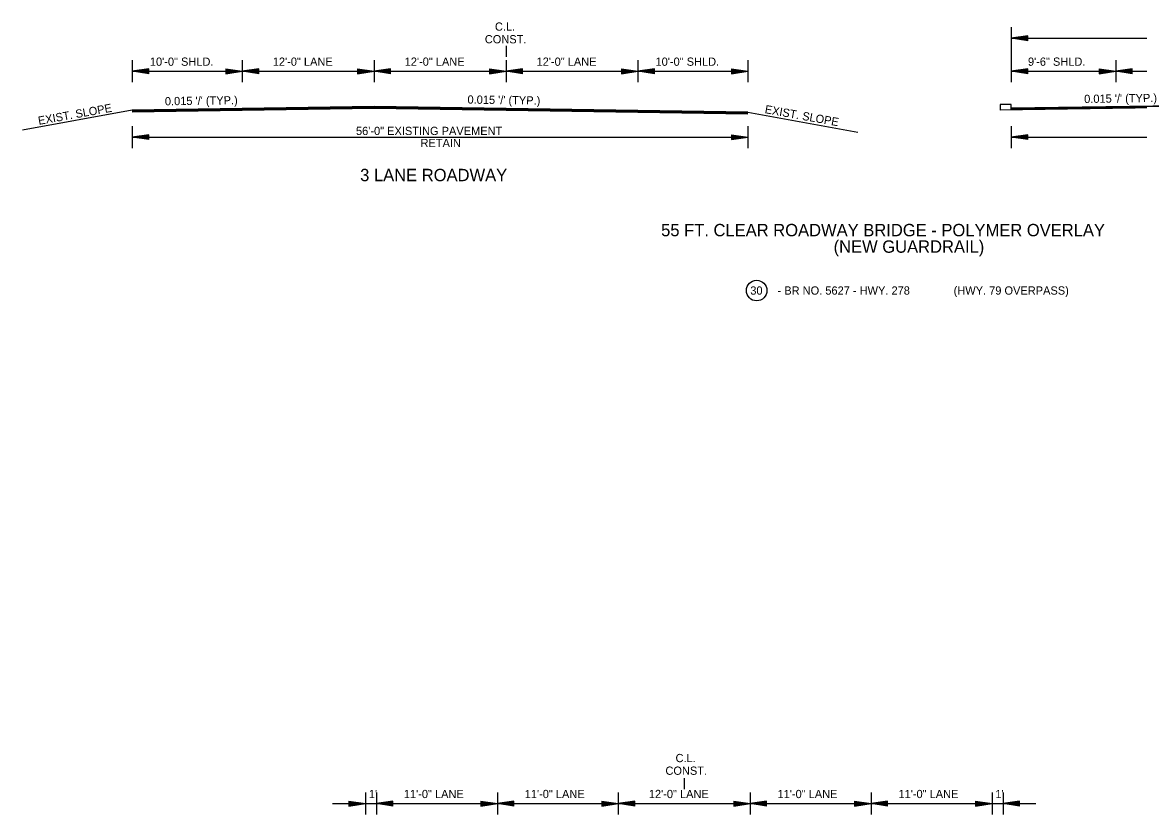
# Model space of a CAD drawing. Extents: x 545241 to 1930787, y -1971772 to 596640.
# Drawn here: x 546726 to 547742, y -1961819 to -1961098 of the extents above; entities that cross this region are included whole.
import ezdxf

# ---------------------------------------------------------------- set-up
doc = ezdxf.new("R2010")
doc.units = 0
doc.layers.add('R_Border', color=7, linetype='Continuous')
doc.layers.add('R_Draft', color=7, linetype='Continuous')

msp = doc.modelspace()

# ---------------------------------------------------------------- linework, layer by layer
at = {"layer": 'R_Border'}
for p, q in [((547625.6, -1961102.6), (547625.6, -1961152.6)), ((547640.6, -1961110.3), (547625.6, -1961112.6)), ((547625.6, -1961112.6), (548175.6, -1961112.6)), ((547640.6, -1961114.8), (547625.6, -1961112.6)), ((547640.6, -1961110.7), (547628.1, -1961112.6)), ((547640.6, -1961114.5), (547628.1, -1961112.6)), ((547640.6, -1961111.1), (547630.7, -1961112.6)), ((547640.6, -1961114.1), (547630.7, -1961112.6)), ((547640.6, -1961111.5), (547633.2, -1961112.6)), ((547640.6, -1961113.7), (547633.2, -1961112.6)), ((547640.6, -1961111.9), (547635.8, -1961112.6)), ((547640.6, -1961113.3), (547635.8, -1961112.6)), ((547640.6, -1961112.2), (547638.3, -1961112.6)), ((547640.6, -1961112.9), (547638.3, -1961112.6)), ((547640.6, -1961114.8), (547640.6, -1961110.3)), ((547166, -1961119.6), (547166, -1961129.6)), ((546826, -1961132.6), (546826, -1961152.6)), ((546926, -1961132.6), (546926, -1961152.6)), ((547046, -1961132.6), (547046, -1961152.6)), ((547166, -1961132.6), (547166, -1961152.6)), ((547286, -1961132.6), (547286, -1961152.6)), ((547386, -1961132.6), (547386, -1961152.6)), ((547720.6, -1961132.6), (547720.6, -1961152.6)), ((546841, -1961140.3), (546826, -1961142.6)), ((546826, -1961142.6), (547386, -1961142.6)), ((546841, -1961144.8), (546826, -1961142.6)), ((546841, -1961140.7), (546828.5, -1961142.6)), ((546841, -1961144.5), (546828.5, -1961142.6)), ((546841, -1961141.1), (546831.1, -1961142.6)), ((546841, -1961144.1), (546831.1, -1961142.6)), ((546841, -1961141.5), (546833.6, -1961142.6)), ((546841, -1961143.7), (546833.6, -1961142.6)), ((546841, -1961141.9), (546836.1, -1961142.6)), ((546841, -1961143.3), (546836.1, -1961142.6)), ((546841, -1961142.2), (546838.6, -1961142.6)), ((546841, -1961142.9), (546838.6, -1961142.6)), ((546841, -1961144.8), (546841, -1961140.3)), ((546911, -1961140.3), (546926, -1961142.6)), ((546911, -1961140.3), (546911, -1961144.8)), ((546911, -1961140.7), (546923.5, -1961142.6)), ((546911, -1961141.1), (546920.9, -1961142.6)), ((546911, -1961141.5), (546918.4, -1961142.6)), ((546911, -1961141.9), (546915.9, -1961142.6)), ((546911, -1961142.2), (546913.3, -1961142.6)), ((546911, -1961144.8), (546926, -1961142.6)), ((546911, -1961143.3), (546915.9, -1961142.6)), ((546911, -1961144.1), (546920.9, -1961142.6)), ((546911, -1961144.5), (546923.5, -1961142.6)), ((546911, -1961143.7), (546918.4, -1961142.6)), ((546911, -1961142.9), (546913.3, -1961142.6)), ((546941, -1961140.3), (546926, -1961142.6)), ((546941, -1961144.8), (546926, -1961142.6)), ((546941, -1961140.7), (546928.5, -1961142.6)), ((546941, -1961144.5), (546928.5, -1961142.6)), ((546941, -1961141.1), (546931.1, -1961142.6)), ((546941, -1961144.1), (546931.1, -1961142.6)), ((546941, -1961141.5), (546933.6, -1961142.6)), ((546941, -1961143.7), (546933.6, -1961142.6)), ((546941, -1961141.9), (546936.1, -1961142.6)), ((546941, -1961143.3), (546936.1, -1961142.6)), ((546941, -1961142.2), (546938.6, -1961142.6)), ((546941, -1961142.9), (546938.6, -1961142.6)), ((546941, -1961144.8), (546941, -1961140.3)), ((547031, -1961140.3), (547046, -1961142.6)), ((547031, -1961140.3), (547031, -1961144.8)), ((547031, -1961140.7), (547043.5, -1961142.6)), ((547031, -1961141.1), (547040.9, -1961142.6)), ((547031, -1961141.5), (547038.4, -1961142.6)), ((547031, -1961141.9), (547035.9, -1961142.6)), ((547031, -1961142.2), (547033.3, -1961142.6)), ((547031, -1961144.8), (547046, -1961142.6)), ((547031, -1961143.3), (547035.9, -1961142.6)), ((547031, -1961144.1), (547040.9, -1961142.6)), ((547031, -1961144.5), (547043.5, -1961142.6)), ((547031, -1961143.7), (547038.4, -1961142.6)), ((547031, -1961142.9), (547033.3, -1961142.6)), ((547061, -1961140.3), (547046, -1961142.6)), ((547061, -1961144.8), (547046, -1961142.6)), ((547061, -1961140.7), (547048.5, -1961142.6)), ((547061, -1961144.5), (547048.5, -1961142.6)), ((547061, -1961141.1), (547051.1, -1961142.6)), ((547061, -1961144.1), (547051.1, -1961142.6)), ((547061, -1961141.5), (547053.6, -1961142.6)), ((547061, -1961143.7), (547053.6, -1961142.6)), ((547061, -1961141.9), (547056.1, -1961142.6)), ((547061, -1961143.3), (547056.1, -1961142.6)), ((547061, -1961142.2), (547058.6, -1961142.6)), ((547061, -1961142.9), (547058.6, -1961142.6)), ((547061, -1961144.8), (547061, -1961140.3)), ((547151, -1961140.3), (547166, -1961142.6)), ((547151, -1961140.3), (547151, -1961144.8)), ((547151, -1961140.7), (547163.5, -1961142.6)), ((547151, -1961141.1), (547160.9, -1961142.6)), ((547151, -1961141.5), (547158.4, -1961142.6)), ((547151, -1961141.9), (547155.9, -1961142.6)), ((547151, -1961142.2), (547153.3, -1961142.6)), ((547151, -1961144.8), (547166, -1961142.6)), ((547151, -1961143.3), (547155.9, -1961142.6)), ((547151, -1961144.1), (547160.9, -1961142.6)), ((547151, -1961144.5), (547163.5, -1961142.6)), ((547151, -1961143.7), (547158.4, -1961142.6)), ((547151, -1961142.9), (547153.3, -1961142.6)), ((547181, -1961140.3), (547166, -1961142.6)), ((547181, -1961144.8), (547166, -1961142.6)), ((547181, -1961140.7), (547168.5, -1961142.6)), ((547181, -1961144.5), (547168.5, -1961142.6)), ((547181, -1961141.1), (547171.1, -1961142.6)), ((547181, -1961144.1), (547171.1, -1961142.6)), ((547181, -1961141.5), (547173.6, -1961142.6)), ((547181, -1961143.7), (547173.6, -1961142.6)), ((547181, -1961141.9), (547176.1, -1961142.6)), ((547181, -1961143.3), (547176.1, -1961142.6)), ((547181, -1961142.2), (547178.6, -1961142.6)), ((547181, -1961142.9), (547178.6, -1961142.6)), ((547181, -1961144.8), (547181, -1961140.3)), ((547271, -1961140.3), (547286, -1961142.6)), ((547271, -1961140.3), (547271, -1961144.8)), ((547271, -1961140.7), (547283.5, -1961142.6)), ((547271, -1961141.1), (547280.9, -1961142.6)), ((547271, -1961141.5), (547278.4, -1961142.6)), ((547271, -1961141.9), (547275.9, -1961142.6)), ((547271, -1961142.2), (547273.3, -1961142.6)), ((547271, -1961144.8), (547286, -1961142.6)), ((547271, -1961143.3), (547275.9, -1961142.6)), ((547271, -1961144.1), (547280.9, -1961142.6)), ((547271, -1961144.5), (547283.5, -1961142.6)), ((547271, -1961143.7), (547278.4, -1961142.6)), ((547271, -1961142.9), (547273.3, -1961142.6)), ((547301, -1961140.3), (547286, -1961142.6)), ((547301, -1961144.8), (547286, -1961142.6)), ((547301, -1961140.7), (547288.5, -1961142.6)), ((547301, -1961144.5), (547288.5, -1961142.6)), ((547301, -1961141.1), (547291.1, -1961142.6)), ((547301, -1961144.1), (547291.1, -1961142.6)), ((547301, -1961141.5), (547293.6, -1961142.6)), ((547301, -1961143.7), (547293.6, -1961142.6)), ((547301, -1961141.9), (547296.1, -1961142.6)), ((547301, -1961143.3), (547296.1, -1961142.6)), ((547301, -1961142.2), (547298.6, -1961142.6)), ((547301, -1961142.9), (547298.6, -1961142.6)), ((547301, -1961144.8), (547301, -1961140.3)), ((547371, -1961140.3), (547386, -1961142.6)), ((547371, -1961140.3), (547371, -1961144.8)), ((547371, -1961140.7), (547383.5, -1961142.6)), ((547371, -1961141.1), (547380.9, -1961142.6)), ((547371, -1961141.5), (547378.4, -1961142.6)), ((547371, -1961141.9), (547375.9, -1961142.6)), ((547371, -1961142.2), (547373.3, -1961142.6)), ((547371, -1961144.8), (547386, -1961142.6)), ((547371, -1961143.3), (547375.9, -1961142.6)), ((547371, -1961144.1), (547380.9, -1961142.6)), ((547371, -1961144.5), (547383.5, -1961142.6)), ((547371, -1961143.7), (547378.4, -1961142.6)), ((547371, -1961142.9), (547373.3, -1961142.6)), ((547640.6, -1961140.3), (547625.6, -1961142.6)), ((547625.6, -1961142.6), (548175.6, -1961142.6)), ((547640.6, -1961144.8), (547625.6, -1961142.6)), ((547640.6, -1961140.7), (547628.1, -1961142.6)), ((547640.6, -1961144.5), (547628.1, -1961142.6)), ((547640.6, -1961141.1), (547630.7, -1961142.6)), ((547640.6, -1961144.1), (547630.7, -1961142.6)), ((547640.6, -1961141.5), (547633.2, -1961142.6)), ((547640.6, -1961143.7), (547633.2, -1961142.6)), ((547640.6, -1961141.9), (547635.8, -1961142.6)), ((547640.6, -1961143.3), (547635.8, -1961142.6)), ((547640.6, -1961142.2), (547638.3, -1961142.6)), ((547640.6, -1961142.9), (547638.3, -1961142.6)), ((547640.6, -1961144.8), (547640.6, -1961140.3)), ((547705.6, -1961140.3), (547720.6, -1961142.6)), ((547705.6, -1961140.3), (547705.6, -1961144.8)), ((547705.6, -1961140.7), (547718.1, -1961142.6)), ((547705.6, -1961141.1), (547715.5, -1961142.6)), ((547705.6, -1961141.5), (547713, -1961142.6)), ((547705.6, -1961141.9), (547710.5, -1961142.6)), ((547705.6, -1961142.2), (547708, -1961142.6)), ((547705.6, -1961144.8), (547720.6, -1961142.6)), ((547705.6, -1961143.3), (547710.5, -1961142.6)), ((547705.6, -1961144.1), (547715.5, -1961142.6)), ((547705.6, -1961144.5), (547718.1, -1961142.6)), ((547705.6, -1961143.7), (547713, -1961142.6)), ((547705.6, -1961142.9), (547708, -1961142.6)), ((547735.6, -1961140.3), (547720.6, -1961142.6)), ((547735.6, -1961144.8), (547720.6, -1961142.6)), ((547735.6, -1961140.7), (547723.1, -1961142.6)), ((547735.6, -1961144.5), (547723.1, -1961142.6)), ((547735.6, -1961141.1), (547725.7, -1961142.6)), ((547735.6, -1961144.1), (547725.7, -1961142.6)), ((547735.6, -1961141.5), (547728.2, -1961142.6)), ((547735.6, -1961143.7), (547728.2, -1961142.6)), ((547735.6, -1961141.9), (547730.8, -1961142.6)), ((547735.6, -1961143.3), (547730.8, -1961142.6)), ((547735.6, -1961142.2), (547733.3, -1961142.6)), ((547735.6, -1961142.9), (547733.3, -1961142.6)), ((547735.6, -1961144.8), (547735.6, -1961140.3)), ((546826, -1961178.1), (546726, -1961196.1)), ((547386, -1961179.9), (547486, -1961197.9)), ((546826, -1961192.6), (546826, -1961212.6)), ((547386, -1961192.6), (547386, -1961212.6)), ((547625.6, -1961192.6), (547625.6, -1961212.6)), ((546841, -1961200.3), (546826, -1961202.6)), ((546826, -1961202.6), (547386, -1961202.6)), ((546841, -1961204.8), (546826, -1961202.6)), ((546841, -1961200.7), (546828.5, -1961202.6)), ((546841, -1961204.5), (546828.5, -1961202.6)), ((546841, -1961201.1), (546831.1, -1961202.6)), ((546841, -1961204.1), (546831.1, -1961202.6)), ((546841, -1961201.5), (546833.6, -1961202.6)), ((546841, -1961203.7), (546833.6, -1961202.6)), ((546841, -1961201.9), (546836.1, -1961202.6)), ((546841, -1961203.3), (546836.1, -1961202.6)), ((546841, -1961202.2), (546838.6, -1961202.6)), ((546841, -1961202.9), (546838.6, -1961202.6)), ((546841, -1961204.8), (546841, -1961200.3)), ((547371, -1961200.3), (547386, -1961202.6)), ((547371, -1961200.3), (547371, -1961204.8)), ((547371, -1961200.7), (547383.5, -1961202.6)), ((547371, -1961201.1), (547380.9, -1961202.6)), ((547371, -1961201.5), (547378.4, -1961202.6)), ((547371, -1961201.9), (547375.9, -1961202.6)), ((547371, -1961202.2), (547373.3, -1961202.6)), ((547371, -1961204.8), (547386, -1961202.6)), ((547371, -1961203.3), (547375.9, -1961202.6)), ((547371, -1961204.1), (547380.9, -1961202.6)), ((547371, -1961204.5), (547383.5, -1961202.6)), ((547371, -1961203.7), (547378.4, -1961202.6)), ((547371, -1961202.9), (547373.3, -1961202.6)), ((547640.6, -1961200.3), (547625.6, -1961202.6)), ((547625.6, -1961202.6), (548175.6, -1961202.6)), ((547640.6, -1961204.8), (547625.6, -1961202.6)), ((547640.6, -1961200.7), (547628.1, -1961202.6)), ((547640.6, -1961204.5), (547628.1, -1961202.6)), ((547640.6, -1961201.1), (547630.7, -1961202.6)), ((547640.6, -1961204.1), (547630.7, -1961202.6)), ((547640.6, -1961201.5), (547633.2, -1961202.6)), ((547640.6, -1961203.7), (547633.2, -1961202.6)), ((547640.6, -1961201.9), (547635.8, -1961202.6)), ((547640.6, -1961203.3), (547635.8, -1961202.6)), ((547640.6, -1961202.2), (547638.3, -1961202.6)), ((547640.6, -1961202.9), (547638.3, -1961202.6)), ((547640.6, -1961204.8), (547640.6, -1961200.3)), ((547328.1, -1961785.8), (547328.1, -1961795.8)), ((547038.1, -1961798.8), (547038.1, -1961818.8)), ((547048.1, -1961798.8), (547048.1, -1961818.8)), ((547158.1, -1961798.8), (547158.1, -1961818.8)), ((547268.1, -1961798.8), (547268.1, -1961818.8)), ((547388.1, -1961798.8), (547388.1, -1961818.8)), ((547498.1, -1961798.8), (547498.1, -1961818.8)), ((547608.1, -1961798.8), (547608.1, -1961818.8)), ((547618.1, -1961798.8), (547618.1, -1961818.8)), ((547008.1, -1961808.8), (547648.1, -1961808.8)), ((547023.1, -1961806.6), (547038.1, -1961808.8)), ((547023.1, -1961806.6), (547023.1, -1961811.1)), ((547023.1, -1961807), (547035.5, -1961808.8)), ((547023.1, -1961807.4), (547033, -1961808.8)), ((547023.1, -1961807.7), (547030.5, -1961808.8)), ((547023.1, -1961808.1), (547027.9, -1961808.8)), ((547023.1, -1961808.5), (547025.4, -1961808.8)), ((547023.1, -1961811.1), (547038.1, -1961808.8)), ((547023.1, -1961809.6), (547027.9, -1961808.8)), ((547023.1, -1961810.3), (547033, -1961808.8)), ((547023.1, -1961810.7), (547035.5, -1961808.8)), ((547023.1, -1961810), (547030.5, -1961808.8)), ((547023.1, -1961809.2), (547025.4, -1961808.8)), ((547063.1, -1961806.6), (547048.1, -1961808.8)), ((547063.1, -1961811.1), (547048.1, -1961808.8)), ((547063.1, -1961807), (547050.6, -1961808.8)), ((547063.1, -1961810.7), (547050.6, -1961808.8)), ((547063.1, -1961807.4), (547053.1, -1961808.8)), ((547063.1, -1961810.3), (547053.1, -1961808.8)), ((547063.1, -1961807.7), (547055.6, -1961808.8)), ((547063.1, -1961810), (547055.6, -1961808.8)), ((547063.1, -1961808.1), (547058.2, -1961808.8)), ((547063.1, -1961809.6), (547058.2, -1961808.8)), ((547063.1, -1961808.5), (547060.7, -1961808.8)), ((547063.1, -1961809.2), (547060.7, -1961808.8)), ((547063.1, -1961811.1), (547063.1, -1961806.6)), ((547143.1, -1961806.6), (547158.1, -1961808.8)), ((547143.1, -1961806.6), (547143.1, -1961811.1)), ((547143.1, -1961807), (547155.5, -1961808.8)), ((547143.1, -1961807.4), (547153, -1961808.8)), ((547143.1, -1961807.7), (547150.5, -1961808.8)), ((547143.1, -1961808.1), (547147.9, -1961808.8)), ((547143.1, -1961808.5), (547145.4, -1961808.8)), ((547143.1, -1961811.1), (547158.1, -1961808.8)), ((547143.1, -1961809.6), (547147.9, -1961808.8)), ((547143.1, -1961810.3), (547153, -1961808.8)), ((547143.1, -1961810.7), (547155.5, -1961808.8)), ((547143.1, -1961810), (547150.5, -1961808.8)), ((547143.1, -1961809.2), (547145.4, -1961808.8)), ((547173.1, -1961806.6), (547158.1, -1961808.8)), ((547173.1, -1961811.1), (547158.1, -1961808.8)), ((547173.1, -1961807), (547160.6, -1961808.8)), ((547173.1, -1961810.7), (547160.6, -1961808.8)), ((547173.1, -1961807.4), (547163.1, -1961808.8)), ((547173.1, -1961810.3), (547163.1, -1961808.8)), ((547173.1, -1961807.7), (547165.6, -1961808.8)), ((547173.1, -1961810), (547165.6, -1961808.8)), ((547173.1, -1961808.1), (547168.2, -1961808.8)), ((547173.1, -1961809.6), (547168.2, -1961808.8)), ((547173.1, -1961808.5), (547170.7, -1961808.8)), ((547173.1, -1961809.2), (547170.7, -1961808.8)), ((547173.1, -1961811.1), (547173.1, -1961806.6)), ((547253.1, -1961806.6), (547268.1, -1961808.8)), ((547253.1, -1961806.6), (547253.1, -1961811.1)), ((547253.1, -1961807), (547265.5, -1961808.8)), ((547253.1, -1961807.4), (547263, -1961808.8)), ((547253.1, -1961807.7), (547260.5, -1961808.8)), ((547253.1, -1961808.1), (547257.9, -1961808.8)), ((547253.1, -1961808.5), (547255.4, -1961808.8)), ((547253.1, -1961811.1), (547268.1, -1961808.8)), ((547253.1, -1961809.6), (547257.9, -1961808.8)), ((547253.1, -1961810.3), (547263, -1961808.8)), ((547253.1, -1961810.7), (547265.5, -1961808.8)), ((547253.1, -1961810), (547260.5, -1961808.8)), ((547253.1, -1961809.2), (547255.4, -1961808.8)), ((547283.1, -1961806.6), (547268.1, -1961808.8)), ((547283.1, -1961811.1), (547268.1, -1961808.8)), ((547283.1, -1961807), (547270.6, -1961808.8)), ((547283.1, -1961810.7), (547270.6, -1961808.8)), ((547283.1, -1961807.4), (547273.1, -1961808.8)), ((547283.1, -1961810.3), (547273.1, -1961808.8)), ((547283.1, -1961807.7), (547275.6, -1961808.8)), ((547283.1, -1961810), (547275.6, -1961808.8)), ((547283.1, -1961808.1), (547278.2, -1961808.8)), ((547283.1, -1961809.6), (547278.2, -1961808.8)), ((547283.1, -1961808.5), (547280.7, -1961808.8)), ((547283.1, -1961809.2), (547280.7, -1961808.8)), ((547283.1, -1961811.1), (547283.1, -1961806.6)), ((547373.1, -1961806.6), (547388.1, -1961808.8)), ((547373.1, -1961806.6), (547373.1, -1961811.1)), ((547373.1, -1961807), (547385.5, -1961808.8)), ((547373.1, -1961807.4), (547383, -1961808.8)), ((547373.1, -1961807.7), (547380.5, -1961808.8)), ((547373.1, -1961808.1), (547377.9, -1961808.8)), ((547373.1, -1961808.5), (547375.4, -1961808.8)), ((547373.1, -1961811.1), (547388.1, -1961808.8)), ((547373.1, -1961809.6), (547377.9, -1961808.8)), ((547373.1, -1961810.3), (547383, -1961808.8)), ((547373.1, -1961810.7), (547385.5, -1961808.8)), ((547373.1, -1961810), (547380.5, -1961808.8)), ((547373.1, -1961809.2), (547375.4, -1961808.8)), ((547403.1, -1961806.6), (547388.1, -1961808.8)), ((547403.1, -1961811.1), (547388.1, -1961808.8)), ((547403.1, -1961807), (547390.6, -1961808.8)), ((547403.1, -1961810.7), (547390.6, -1961808.8)), ((547403.1, -1961807.4), (547393.1, -1961808.8)), ((547403.1, -1961810.3), (547393.1, -1961808.8)), ((547403.1, -1961807.7), (547395.6, -1961808.8)), ((547403.1, -1961810), (547395.6, -1961808.8)), ((547403.1, -1961808.1), (547398.2, -1961808.8)), ((547403.1, -1961809.6), (547398.2, -1961808.8)), ((547403.1, -1961808.5), (547400.7, -1961808.8)), ((547403.1, -1961809.2), (547400.7, -1961808.8)), ((547403.1, -1961811.1), (547403.1, -1961806.6)), ((547483.1, -1961806.6), (547498.1, -1961808.8)), ((547483.1, -1961806.6), (547483.1, -1961811.1)), ((547483.1, -1961807), (547495.5, -1961808.8)), ((547483.1, -1961807.4), (547493, -1961808.8)), ((547483.1, -1961807.7), (547490.5, -1961808.8)), ((547483.1, -1961808.1), (547487.9, -1961808.8)), ((547483.1, -1961808.5), (547485.4, -1961808.8)), ((547483.1, -1961811.1), (547498.1, -1961808.8)), ((547483.1, -1961809.6), (547487.9, -1961808.8)), ((547483.1, -1961810.3), (547493, -1961808.8)), ((547483.1, -1961810.7), (547495.5, -1961808.8)), ((547483.1, -1961810), (547490.5, -1961808.8)), ((547483.1, -1961809.2), (547485.4, -1961808.8)), ((547513.1, -1961806.6), (547498.1, -1961808.8)), ((547513.1, -1961811.1), (547498.1, -1961808.8)), ((547513.1, -1961807), (547500.6, -1961808.8)), ((547513.1, -1961810.7), (547500.6, -1961808.8)), ((547513.1, -1961807.4), (547503.1, -1961808.8)), ((547513.1, -1961810.3), (547503.1, -1961808.8)), ((547513.1, -1961807.7), (547505.6, -1961808.8)), ((547513.1, -1961810), (547505.6, -1961808.8)), ((547513.1, -1961808.1), (547508.2, -1961808.8)), ((547513.1, -1961809.6), (547508.2, -1961808.8)), ((547513.1, -1961808.5), (547510.7, -1961808.8)), ((547513.1, -1961809.2), (547510.7, -1961808.8)), ((547513.1, -1961811.1), (547513.1, -1961806.6)), ((547593.1, -1961806.6), (547608.1, -1961808.8)), ((547593.1, -1961806.6), (547593.1, -1961811.1)), ((547593.1, -1961807), (547605.5, -1961808.8)), ((547593.1, -1961807.4), (547603, -1961808.8)), ((547593.1, -1961807.7), (547600.5, -1961808.8)), ((547593.1, -1961808.1), (547597.9, -1961808.8)), ((547593.1, -1961808.5), (547595.4, -1961808.8)), ((547593.1, -1961811.1), (547608.1, -1961808.8)), ((547593.1, -1961809.6), (547597.9, -1961808.8)), ((547593.1, -1961810.3), (547603, -1961808.8)), ((547593.1, -1961810.7), (547605.5, -1961808.8)), ((547593.1, -1961810), (547600.5, -1961808.8)), ((547593.1, -1961809.2), (547595.4, -1961808.8)), ((547633.1, -1961806.6), (547618.1, -1961808.8)), ((547633.1, -1961811.1), (547618.1, -1961808.8)), ((547633.1, -1961807), (547620.6, -1961808.8)), ((547633.1, -1961810.7), (547620.6, -1961808.8)), ((547633.1, -1961807.4), (547623.1, -1961808.8)), ((547633.1, -1961810.3), (547623.1, -1961808.8)), ((547633.1, -1961807.7), (547625.6, -1961808.8)), ((547633.1, -1961810), (547625.6, -1961808.8)), ((547633.1, -1961808.1), (547628.2, -1961808.8)), ((547633.1, -1961809.6), (547628.2, -1961808.8)), ((547633.1, -1961808.5), (547630.7, -1961808.8)), ((547633.1, -1961809.2), (547630.7, -1961808.8)), ((547633.1, -1961811.1), (547633.1, -1961806.6))]:
    msp.add_line(p, q, dxfattribs=at)
for points in [[(547386, -1961179.9), (547046, -1961174.8), (546826, -1961178.1)], [(547386, -1961180.2), (547046, -1961175.1), (546826, -1961178.4)], [(547386, -1961180.5), (547046, -1961175.4), (546826, -1961178.7)], [(547386, -1961180.8), (547046, -1961175.7), (546826, -1961179)], [(547386, -1961181.1), (547046, -1961176), (546826, -1961179.3)], [(547386, -1961181.4), (547046, -1961176.3), (546826, -1961179.6)], [(547386, -1961181.7), (547046, -1961176.6), (546826, -1961179.9)], [(547625.6, -1961177.7), (547625.6, -1961172.7), (547615.6, -1961172.7), (547615.6, -1961178.1)], [(548185.6, -1961179.9), (547840.6, -1961174.8), (547615.6, -1961178.1)], [(548175.6, -1961178), (547840.6, -1961173), (547625.6, -1961176.2)], [(548175.6, -1961178.3), (547840.6, -1961173.3), (547625.6, -1961176.5)], [(548175.6, -1961178.6), (547840.6, -1961173.6), (547625.6, -1961176.8)], [(548175.6, -1961178.9), (547840.6, -1961173.9), (547625.6, -1961177.1)], [(548175.6, -1961179.2), (547840.6, -1961174.2), (547625.6, -1961177.4)], [(548175.6, -1961179.5), (547840.6, -1961174.5), (547625.6, -1961177.7)]]:
    msp.add_lwpolyline(points, dxfattribs=at)
msp.add_circle((547394, -1961342.1), 9.34, dxfattribs=at)

# ---------------------------------------------------------------- texts
for s, height, p in [('C.L.', 7.5, (547155.9, -1961105.7)), ('CONST.', 7.5, (547146.7, -1961117.2)), ('10\'-0" SHLD.', 7.5, (546842, -1961137.6)), ('12\'-0" LANE', 7.5, (546953.8, -1961137.6)), ('12\'-0" LANE', 7.5, (547073.8, -1961137.6)), ('12\'-0" LANE', 7.5, (547193.8, -1961137.6)), ('10\'-0" SHLD.', 7.5, (547302, -1961137.6)), ('9\'-6" SHLD.', 7.5, (547640.8, -1961137.6)), ('56\'-0" EXISTING PAVEMENT', 7.5, (547029.5, -1961200.6)), ('RETAIN', 7.5, (547088.2, -1961211.6)), ('3 LANE ROADWAY', 11.25, (547033.3, -1961242.6)), ('55 FT. CLEAR ROADWAY BRIDGE - POLYMER OVERLAY', 11.25, (547307.1, -1961292.7)), ('(NEW GUARDRAIL)', 11.25, (547464, -1961307.7)), ('30', 7.5, (547388.2, -1961345.8)), ('- BR NO. 5627 - HWY. 278', 7.5, (547413, -1961345.8)), ('C.L.', 7.5, (547320.2, -1961771.1)), ('CONST.', 7.5, (547311, -1961782.6)), ("1'", 7.5, (547041.2, -1961803.8)), ('11\'-0" LANE', 7.5, (547073, -1961803.8)), ('11\'-0" LANE', 7.5, (547183, -1961803.8)), ('12\'-0" LANE', 7.5, (547295.9, -1961803.8)), ('11\'-0" LANE', 7.5, (547413, -1961803.8)), ('11\'-0" LANE', 7.5, (547523, -1961803.8)), ("1'", 7.5, (547611.2, -1961803.8))]:
    msp.add_text(s, height=height, dxfattribs=at).set_placement(p)
for s, rotation, p in [("0.015 '/' (TYP.)", 0.8594, (546855.7, -1961173.6)), ("0.015 '/' (TYP.)", 359.1406, (547130.9, -1961172)), ("0.015 '/' (TYP.)", 0.8594, (547692, -1961171.5)), ('EXIST. SLOPE', 10.204, (546741, -1961191.4)), ('EXIST. SLOPE', 349.796, (547401, -1961180.6))]:
    msp.add_text(s, height=7.5, rotation=rotation, dxfattribs=at).set_placement(p)
at = {"layer": 'R_Draft'}
msp.add_text('(HWY. 79 OVERPASS)', height=7.5, dxfattribs=at).set_placement((547573.2, -1961345.8))

doc.saveas('drawing.dxf')
